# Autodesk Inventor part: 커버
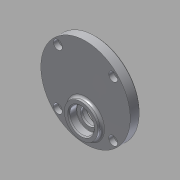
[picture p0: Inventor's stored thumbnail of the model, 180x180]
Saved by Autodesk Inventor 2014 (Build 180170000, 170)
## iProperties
Created: 2015-07
Part Number: 커버
Material: 알루미늄 6061
Document SubType Name: Modeling
Designer: Administrator
Density: 2.71 g/cm^3
Appearance: 알루미늄 - 평지
Mass: 113.906 g
Surface Area: 144.875 cm^2
Volume: 42.0316 cm^3
Author: Administrator
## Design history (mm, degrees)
sketch "스케치1"
  geometry: C1 r 40 at (0, 0); 1 further point
  constraints: 1 centre point, 1 coincident
  dimensions: "d0" = 80 diameter of C1
extrude "돌출1" new body sketch "스케치1" distance "d1" = 9; taper "d2" = 0 deg
sketch "스케치2"
  geometry: C1 r 40 at (0, 0) reference; C2 r 15 at (0, -20)
  constraints: 1 centre point, 1 vertical alignment
  dimensions: "d3" = 20 distance of C1.centre C2.centre; "d4" = 30 diameter of C2
extrude "돌출2" join sketch "스케치2" distance "d5" = 4; taper "d6" = 0 deg
sketch "스케치3"
  geometry: C1 r 40 at (0, 0) reference; C2 r 14 at (0, -11); C3 r 14 at (0, 20)
  constraints: 2 centre point, 2 vertical alignment
  dimensions: "d7" = 11 distance of C1.centre C2.centre; "d8" = 20 distance of C1.centre C3.centre; "d9" = 28 diameter of C3; "d10" = 28 diameter of C2
extrude "돌출3" join sketch "스케치3" distance "d11" = 3; taper "d12" = 0 deg
sketch "스케치4"
  geometry: C1 r 15 at (0, 0) reference; C2 r 11 at (0, 0); 1 further point
  constraints: 1 centre point, 1 coincident
  dimensions: "d13" = 22 diameter of C2
extrude "돌출4" cut sketch "스케치4" distance "d14" = 7; taper "d15" = 0 deg
sketch "스케치5"
  geometry: C1 r 14 at (0, 0) reference; C2 r 11 at (0, 0); 1 further point
  constraints: 1 centre point, 1 coincident
  dimensions: "d16" = 22 diameter of C2
extrude "돌출5" cut sketch "스케치5" distance "d17" = 7; taper "d18" = 0 deg
sketch "스케치6"
  geometry: C1 r 11 at (0, 0) reference; C2 r 7.5 at (0, 0); 1 further point
  constraints: 1 centre point, 1 coincident
  dimensions: "d19" = 15 diameter of C2
extrude "돌출6" cut sketch "스케치6" distance "d20" = 2; taper "d21" = 0 deg
sketch "스케치7"
  geometry: C1 r 14 at (0, 0) reference; C2 r 11 at (0, 0); 1 further point
  constraints: 1 centre point, 1 coincident
  dimensions: "d22" = 22 diameter of C2
extrude "돌출7" cut sketch "스케치7" distance "d23" = 7; taper "d24" = 0 deg
sketch "스케치8"
  geometry: C1 r 9 at (0, 0); 2 further points
  constraints: 1 centre point, 1 coincident, 1 vertical alignment
  dimensions: "d25" = 18 diameter of C1
extrude "돌출8" cut sketch "스케치8" distance "d26" = 1; taper "d27" = 0 deg
sketch "스케치9"
  geometry: L1 (0, 0)-(28.284, 28.284); L2 (0, 0)-(35, 0); C1 r 4 at (24.749, 24.749); A1 r 35 centre (0, 0) between (35, 0) and (24.749, 24.749)
  constraints: 4 end point, 2 centre point, 2 point on circle, 1 coincident, 1 horizontal, 1 point on line, 2 other
  dimensions: "d28" = 70 diameter of A1; "d29" = 45 deg angle of L2 L1; "d30" = 8 diameter of C1
extrude "돌출9" cut sketch "스케치9" distance "d31" = 4.4; taper "d32" = 0 deg
sketch "스케치10"
  geometry: C1 r 4 at (0, 0) reference; C2 r 2.25 at (0, 0); 1 further point
  constraints: 1 centre point, 1 coincident
  dimensions: "d33" = 4.5 diameter of C2
extrude "돌출10" cut sketch "스케치10" stored distance "d34" = 4.4; taper "d35" = 0 deg
chamfer "모따기1" distance "d39" = 1; stored, may be unused: second distance "d40" = 2, angle "d41" = 45 deg
fillet "모깎기1" dims "d42" = 0.3
fillet "모깎기2" dims "d43" = 2
chamfer "모따기2" distance "d44" = 1; stored, may be unused: second distance "d45" = 2, angle "d46" = 45 deg
fillet "모깎기3" dims "d47" = 2
node "솔리드1"
pattern_circular "원형 패턴1" dims angle "d37" = 360 deg
